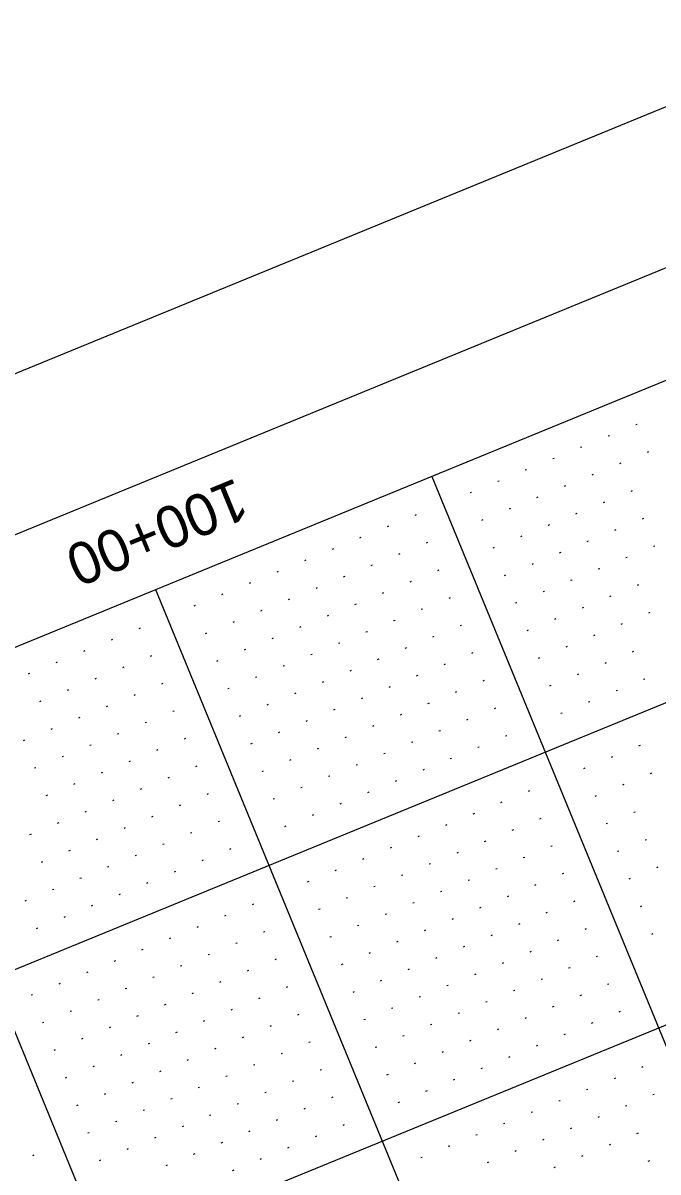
# Model space of a CAD drawing. Extents: x 2148770 to 2150891, y 142633 to 144465.
# Drawn here: x 2149510.3 to 2149616.7, y 143849.5 to 144042.2 of the extents above; entities that cross this region are included whole.
import ezdxf

# ---------------------------------------------------------------- set-up
doc = ezdxf.new("R2010")
doc.units = 0
for name, color, linetype in [('SHT_Plan_Profile_Sheet_Sta_Txt', 7, 'Continuous'), ('SHT_Plot_Shape_Half', 7, 'Continuous'), ('SHT_Profile_Grid_Major', 7, 'Continuous'), ('SHT_Profile_Grid_Minor', 7, 'Continuous'), ('SHT_Sheet_Border', 7, 'Continuous')]:
    doc.layers.add(name, color=color, linetype=linetype)

msp = doc.modelspace()

# ---------------------------------------------------------------- linework, layer by layer
at = {"layer": 'SHT_Plot_Shape_Half'}
msp.add_lwpolyline([(2150799.14, 143324.02), (2149226.52, 142678.36), (2148808.74, 143695.93), (2150381.36, 144341.59)], close=True, dxfattribs=at)
at = {"layer": 'SHT_Profile_Grid_Major'}
for p, q in [((2150326.3, 144218.99), (2148869.31, 143620.81)), ((2150345.29, 144172.74), (2148888.3, 143574.55)), ((2149578.81, 143966.15), (2149751.62, 143545.25)), ((2149532.56, 143947.16), (2149722.46, 143484.63)), ((2149532.56, 143947.16), (2149722.46, 143484.63)), ((2149486.31, 143928.17), (2149676.21, 143465.64))]:
    msp.add_line(p, q, dxfattribs=at)
at = {"layer": 'SHT_Profile_Grid_Minor'}
for p, q in [((2149613.21, 143974.87), (2149612.97, 143974.77)), ((2149608.58, 143972.97), (2149608.35, 143972.87)), ((2149603.96, 143971.07), (2149603.72, 143970.97)), ((2149599.33, 143969.17), (2149599.1, 143969.08)), ((2149615.1, 143970.24), (2149614.87, 143970.15)), ((2149594.7, 143967.27), (2149594.47, 143967.18)), ((2149610.48, 143968.34), (2149610.25, 143968.25)), ((2149590.08, 143965.37), (2149589.85, 143965.28)), ((2149605.85, 143966.44), (2149605.62, 143966.35)), ((2149585.45, 143963.47), (2149585.22, 143963.38)), ((2149601.23, 143964.55), (2149601, 143964.45)), ((2149612.38, 143963.72), (2149612.15, 143963.62)), ((2149596.6, 143962.65), (2149596.37, 143962.55)), ((2149607.75, 143961.82), (2149607.52, 143961.72)), ((2149576.2, 143959.68), (2149575.97, 143959.58)), ((2149591.98, 143960.75), (2149591.75, 143960.65)), ((2149603.13, 143959.92), (2149602.9, 143959.82)), ((2149571.58, 143957.78), (2149571.35, 143957.68)), ((2149587.35, 143958.85), (2149587.12, 143958.75)), ((2149598.5, 143958.02), (2149598.27, 143957.93)), ((2149614.28, 143959.09), (2149614.05, 143959)), ((2149566.95, 143955.88), (2149566.72, 143955.78)), ((2149593.88, 143956.12), (2149593.65, 143956.03)), ((2149605.03, 143955.29), (2149604.8, 143955.2)), ((2149609.65, 143957.19), (2149609.42, 143957.1)), ((2149562.33, 143953.98), (2149562.1, 143953.88)), ((2149578.1, 143955.05), (2149577.87, 143954.96)), ((2149589.25, 143954.22), (2149589.02, 143954.13)), ((2149600.4, 143953.4), (2149600.17, 143953.3)), ((2149616.18, 143954.47), (2149615.95, 143954.37)), ((2149557.7, 143952.08), (2149557.47, 143951.98)), ((2149573.48, 143953.15), (2149573.25, 143953.06)), ((2149595.78, 143951.5), (2149595.54, 143951.4)), ((2149611.55, 143952.57), (2149611.32, 143952.47)), ((2149553.08, 143950.18), (2149552.85, 143950.09)), ((2149568.85, 143951.25), (2149568.62, 143951.16)), ((2149580, 143950.42), (2149579.77, 143950.33)), ((2149591.15, 143949.6), (2149590.92, 143949.5)), ((2149606.93, 143950.67), (2149606.69, 143950.57)), ((2149548.45, 143948.28), (2149548.22, 143948.19)), ((2149564.23, 143949.35), (2149563.99, 143949.26)), ((2149575.38, 143948.53), (2149575.14, 143948.43)), ((2149602.3, 143948.77), (2149602.07, 143948.68)), ((2149613.45, 143947.94), (2149613.22, 143947.85)), ((2149543.83, 143946.38), (2149543.59, 143946.29)), ((2149559.6, 143947.45), (2149559.37, 143947.36)), ((2149570.75, 143946.63), (2149570.52, 143946.53)), ((2149581.9, 143945.8), (2149581.67, 143945.7)), ((2149597.68, 143946.87), (2149597.44, 143946.78)), ((2149608.82, 143946.04), (2149608.59, 143945.95)), ((2149539.2, 143944.48), (2149538.97, 143944.39)), ((2149554.98, 143945.56), (2149554.74, 143945.46)), ((2149566.13, 143944.73), (2149565.89, 143944.63)), ((2149577.27, 143943.9), (2149577.04, 143943.81)), ((2149593.05, 143944.97), (2149592.82, 143944.88)), ((2149604.2, 143944.14), (2149603.97, 143944.05)), ((2149550.35, 143943.66), (2149550.12, 143943.56)), ((2149561.5, 143942.83), (2149561.27, 143942.73)), ((2149572.65, 143942), (2149572.42, 143941.91)), ((2149599.57, 143942.25), (2149599.34, 143942.15)), ((2149615.35, 143943.32), (2149615.12, 143943.22)), ((2149529.95, 143940.69), (2149529.72, 143940.59)), ((2149545.72, 143941.76), (2149545.49, 143941.66)), ((2149556.87, 143940.93), (2149556.64, 143940.83)), ((2149568.02, 143940.1), (2149567.79, 143940.01)), ((2149583.8, 143941.17), (2149583.57, 143941.08)), ((2149594.95, 143940.35), (2149594.72, 143940.25)), ((2149610.72, 143941.42), (2149610.49, 143941.32)), ((2149525.32, 143938.79), (2149525.09, 143938.69)), ((2149541.1, 143939.86), (2149540.87, 143939.76)), ((2149552.25, 143939.03), (2149552.02, 143938.94)), ((2149563.4, 143938.2), (2149563.17, 143938.11)), ((2149579.17, 143939.28), (2149578.94, 143939.18)), ((2149606.1, 143939.52), (2149605.87, 143939.42)), ((2149520.7, 143936.89), (2149520.47, 143936.79)), ((2149531.85, 143936.06), (2149531.62, 143935.97)), ((2149547.62, 143937.13), (2149547.39, 143937.04)), ((2149558.77, 143936.3), (2149558.54, 143936.21)), ((2149574.55, 143937.38), (2149574.32, 143937.28)), ((2149585.7, 143936.55), (2149585.47, 143936.45)), ((2149601.47, 143937.62), (2149601.24, 143937.53)), ((2149612.62, 143936.79), (2149612.39, 143936.7)), ((2149516.07, 143934.99), (2149515.84, 143934.89)), ((2149527.22, 143934.16), (2149526.99, 143934.07)), ((2149543, 143935.23), (2149542.77, 143935.14)), ((2149554.15, 143934.41), (2149553.92, 143934.31)), ((2149569.92, 143935.48), (2149569.69, 143935.38)), ((2149581.07, 143934.65), (2149580.84, 143934.55)), ((2149596.85, 143935.72), (2149596.62, 143935.63)), ((2149608, 143934.89), (2149607.77, 143934.8)), ((2149511.45, 143933.09), (2149511.22, 143932.99)), ((2149522.6, 143932.26), (2149522.37, 143932.17)), ((2149549.52, 143932.51), (2149549.29, 143932.41)), ((2149565.3, 143933.58), (2149565.07, 143933.48)), ((2149576.45, 143932.75), (2149576.22, 143932.66)), ((2149603.37, 143933), (2149603.14, 143932.9)), ((2149517.97, 143930.36), (2149517.74, 143930.27)), ((2149533.75, 143931.43), (2149533.52, 143931.34)), ((2149544.9, 143930.61), (2149544.67, 143930.51)), ((2149560.67, 143931.68), (2149560.44, 143931.58)), ((2149571.82, 143930.85), (2149571.59, 143930.76)), ((2149587.6, 143931.92), (2149587.37, 143931.83)), ((2149598.75, 143931.1), (2149598.52, 143931)), ((2149609.9, 143930.27), (2149609.67, 143930.17)), ((2149614.52, 143932.17), (2149614.29, 143932.07)), ((2149513.35, 143928.46), (2149513.12, 143928.37)), ((2149529.12, 143929.54), (2149528.89, 143929.44)), ((2149556.05, 143929.78), (2149555.82, 143929.69)), ((2149567.2, 143928.95), (2149566.97, 143928.86)), ((2149582.97, 143930.02), (2149582.74, 143929.93)), ((2149605.27, 143928.37), (2149605.04, 143928.27)), ((2149524.5, 143927.64), (2149524.27, 143927.54)), ((2149535.65, 143926.81), (2149535.42, 143926.71)), ((2149551.42, 143927.88), (2149551.19, 143927.79)), ((2149562.57, 143927.05), (2149562.34, 143926.96)), ((2149578.35, 143928.13), (2149578.12, 143928.03)), ((2149589.5, 143927.3), (2149589.26, 143927.2)), ((2149600.65, 143926.47), (2149600.41, 143926.38)), ((2149519.87, 143925.74), (2149519.64, 143925.64)), ((2149531.02, 143924.91), (2149530.79, 143924.82)), ((2149546.8, 143925.98), (2149546.57, 143925.89)), ((2149557.95, 143925.15), (2149557.71, 143925.06)), ((2149573.72, 143926.23), (2149573.49, 143926.13)), ((2149584.87, 143925.4), (2149584.64, 143925.3)), ((2149515.25, 143923.84), (2149515.02, 143923.74)), ((2149526.4, 143923.01), (2149526.16, 143922.92)), ((2149553.32, 143923.26), (2149553.09, 143923.16)), ((2149569.1, 143924.33), (2149568.86, 143924.23)), ((2149580.25, 143923.5), (2149580.01, 143923.41)), ((2149591.4, 143922.67), (2149591.16, 143922.58)), ((2149510.62, 143921.94), (2149510.39, 143921.84)), ((2149521.77, 143921.11), (2149521.54, 143921.02)), ((2149537.55, 143922.18), (2149537.31, 143922.09)), ((2149548.7, 143921.36), (2149548.46, 143921.26)), ((2149564.47, 143922.43), (2149564.24, 143922.33)), ((2149575.62, 143921.6), (2149575.39, 143921.51)), ((2149586.77, 143920.77), (2149586.54, 143920.68)), ((2149613.69, 143921.02), (2149613.46, 143920.92)), ((2149517.15, 143919.21), (2149516.91, 143919.12)), ((2149532.92, 143920.29), (2149532.69, 143920.19)), ((2149559.85, 143920.53), (2149559.61, 143920.43)), ((2149570.99, 143919.7), (2149570.76, 143919.61)), ((2149582.14, 143918.87), (2149581.91, 143918.78)), ((2149609.07, 143919.12), (2149608.84, 143919.02)), ((2149512.52, 143917.31), (2149512.29, 143917.22)), ((2149528.29, 143918.39), (2149528.06, 143918.29)), ((2149539.44, 143917.56), (2149539.21, 143917.46)), ((2149555.22, 143918.63), (2149554.99, 143918.54)), ((2149566.37, 143917.8), (2149566.14, 143917.71)), ((2149577.52, 143916.98), (2149577.29, 143916.88)), ((2149604.44, 143917.22), (2149604.21, 143917.13)), ((2149523.67, 143916.49), (2149523.44, 143916.39)), ((2149534.82, 143915.66), (2149534.59, 143915.56)), ((2149550.59, 143916.73), (2149550.36, 143916.64)), ((2149561.74, 143915.9), (2149561.51, 143915.81)), ((2149572.89, 143915.08), (2149572.66, 143914.98)), ((2149615.59, 143916.39), (2149615.36, 143916.3)), ((2149519.04, 143914.59), (2149518.81, 143914.49)), ((2149530.19, 143913.76), (2149529.96, 143913.67)), ((2149541.34, 143912.93), (2149541.11, 143912.84)), ((2149557.12, 143914.01), (2149556.89, 143913.91)), ((2149568.27, 143913.18), (2149568.04, 143913.08)), ((2149595.19, 143913.42), (2149594.96, 143913.33)), ((2149610.97, 143914.49), (2149610.74, 143914.4)), ((2149514.42, 143912.69), (2149514.19, 143912.59)), ((2149525.57, 143911.86), (2149525.34, 143911.77)), ((2149536.72, 143911.03), (2149536.49, 143910.94)), ((2149552.49, 143912.11), (2149552.26, 143912.01)), ((2149563.64, 143911.28), (2149563.41, 143911.18)), ((2149590.57, 143911.52), (2149590.34, 143911.43)), ((2149606.34, 143912.59), (2149606.11, 143912.5)), ((2149520.94, 143909.96), (2149520.71, 143909.87)), ((2149532.09, 143909.14), (2149531.86, 143909.04)), ((2149559.02, 143909.38), (2149558.79, 143909.28)), ((2149585.94, 143909.62), (2149585.71, 143909.53)), ((2149612.87, 143909.87), (2149612.64, 143909.77)), ((2149516.32, 143908.06), (2149516.09, 143907.97)), ((2149527.47, 143907.24), (2149527.24, 143907.14)), ((2149543.24, 143908.31), (2149543.01, 143908.21)), ((2149554.39, 143907.48), (2149554.16, 143907.39)), ((2149581.32, 143907.73), (2149581.09, 143907.63)), ((2149597.09, 143908.8), (2149596.86, 143908.7)), ((2149608.24, 143907.97), (2149608.01, 143907.87)), ((2149511.69, 143906.16), (2149511.46, 143906.07)), ((2149522.84, 143905.34), (2149522.61, 143905.24)), ((2149538.62, 143906.41), (2149538.39, 143906.31)), ((2149576.69, 143905.83), (2149576.46, 143905.73)), ((2149592.47, 143906.9), (2149592.24, 143906.8)), ((2149614.77, 143905.24), (2149614.53, 143905.15)), ((2149518.22, 143903.44), (2149517.99, 143903.34)), ((2149533.99, 143904.51), (2149533.76, 143904.42)), ((2149545.14, 143903.68), (2149544.91, 143903.59)), ((2149572.07, 143903.93), (2149571.84, 143903.83)), ((2149587.84, 143905), (2149587.61, 143904.9)), ((2149598.99, 143904.17), (2149598.76, 143904.08)), ((2149610.14, 143903.34), (2149609.91, 143903.25)), ((2149513.59, 143901.54), (2149513.36, 143901.44)), ((2149529.37, 143902.61), (2149529.14, 143902.52)), ((2149540.52, 143901.78), (2149540.29, 143901.69)), ((2149567.44, 143902.03), (2149567.21, 143901.93)), ((2149583.22, 143903.1), (2149582.98, 143903)), ((2149594.37, 143902.27), (2149594.13, 143902.18)), ((2149524.74, 143900.71), (2149524.51, 143900.62)), ((2149535.89, 143899.88), (2149535.66, 143899.79)), ((2149562.82, 143900.13), (2149562.58, 143900.03)), ((2149578.59, 143901.2), (2149578.36, 143901.11)), ((2149589.74, 143900.37), (2149589.51, 143900.28)), ((2149600.89, 143899.55), (2149600.66, 143899.45)), ((2149616.67, 143900.62), (2149616.43, 143900.52)), ((2149520.12, 143898.81), (2149519.88, 143898.72)), ((2149531.27, 143897.99), (2149531.03, 143897.89)), ((2149558.19, 143898.23), (2149557.96, 143898.14)), ((2149573.97, 143899.3), (2149573.73, 143899.21)), ((2149585.12, 143898.47), (2149584.88, 143898.38)), ((2149596.26, 143897.65), (2149596.03, 143897.55)), ((2149612.04, 143898.72), (2149611.81, 143898.62)), ((2149515.49, 143896.91), (2149515.26, 143896.82)), ((2149526.64, 143896.09), (2149526.41, 143895.99)), ((2149569.34, 143897.4), (2149569.11, 143897.31)), ((2149580.49, 143896.58), (2149580.26, 143896.48)), ((2149591.64, 143895.75), (2149591.41, 143895.65)), ((2149510.87, 143895.02), (2149510.63, 143894.92)), ((2149522.01, 143894.19), (2149521.78, 143894.09)), ((2149548.94, 143894.43), (2149548.71, 143894.34)), ((2149564.71, 143895.5), (2149564.48, 143895.41)), ((2149575.86, 143894.68), (2149575.63, 143894.58)), ((2149587.01, 143893.85), (2149586.78, 143893.75)), ((2149602.79, 143894.92), (2149602.56, 143894.83)), ((2149613.94, 143894.09), (2149613.71, 143894)), ((2149517.39, 143892.29), (2149517.16, 143892.19)), ((2149544.31, 143892.53), (2149544.08, 143892.44)), ((2149560.09, 143893.6), (2149559.86, 143893.51)), ((2149571.24, 143892.78), (2149571.01, 143892.68)), ((2149582.39, 143891.95), (2149582.16, 143891.86)), ((2149598.16, 143893.02), (2149597.93, 143892.93)), ((2149512.76, 143890.39), (2149512.53, 143890.29)), ((2149539.69, 143890.63), (2149539.46, 143890.54)), ((2149550.84, 143889.81), (2149550.61, 143889.71)), ((2149566.61, 143890.88), (2149566.38, 143890.78)), ((2149577.76, 143890.05), (2149577.53, 143889.96)), ((2149593.54, 143891.12), (2149593.31, 143891.03)), ((2149604.69, 143890.3), (2149604.46, 143890.2)), ((2149535.06, 143888.74), (2149534.83, 143888.64)), ((2149546.21, 143887.91), (2149545.98, 143887.81)), ((2149561.99, 143888.98), (2149561.76, 143888.88)), ((2149573.14, 143888.15), (2149572.91, 143888.06)), ((2149588.91, 143889.22), (2149588.68, 143889.13)), ((2149600.06, 143888.4), (2149599.83, 143888.3)), ((2149615.84, 143889.47), (2149615.61, 143889.37)), ((2149530.44, 143886.84), (2149530.21, 143886.74)), ((2149541.59, 143886.01), (2149541.36, 143885.91)), ((2149568.51, 143886.25), (2149568.28, 143886.16)), ((2149584.29, 143887.32), (2149584.06, 143887.23)), ((2149595.44, 143886.5), (2149595.21, 143886.4)), ((2149525.81, 143884.94), (2149525.58, 143884.84)), ((2149536.96, 143884.11), (2149536.73, 143884.01)), ((2149552.74, 143885.18), (2149552.51, 143885.09)), ((2149563.89, 143884.35), (2149563.66, 143884.26)), ((2149579.66, 143885.43), (2149579.43, 143885.33)), ((2149590.81, 143884.6), (2149590.58, 143884.5)), ((2149606.59, 143885.67), (2149606.36, 143885.58)), ((2149521.19, 143883.04), (2149520.96, 143882.94)), ((2149532.34, 143882.21), (2149532.11, 143882.12)), ((2149548.11, 143883.28), (2149547.88, 143883.19)), ((2149575.04, 143883.53), (2149574.81, 143883.43)), ((2149586.19, 143882.7), (2149585.96, 143882.6)), ((2149601.96, 143883.77), (2149601.73, 143883.68)), ((2149516.56, 143881.14), (2149516.33, 143881.04)), ((2149527.71, 143880.31), (2149527.48, 143880.22)), ((2149543.49, 143881.38), (2149543.26, 143881.29)), ((2149554.64, 143880.56), (2149554.41, 143880.46)), ((2149570.41, 143881.63), (2149570.18, 143881.53)), ((2149581.56, 143880.8), (2149581.33, 143880.71)), ((2149597.34, 143881.87), (2149597.11, 143881.78)), ((2149608.49, 143881.04), (2149608.25, 143880.95)), ((2149511.94, 143879.24), (2149511.71, 143879.15)), ((2149523.09, 143878.41), (2149522.86, 143878.32)), ((2149538.86, 143879.48), (2149538.63, 143879.39)), ((2149550.01, 143878.66), (2149549.78, 143878.56)), ((2149565.79, 143879.73), (2149565.56, 143879.63)), ((2149576.94, 143878.9), (2149576.7, 143878.81)), ((2149592.71, 143879.97), (2149592.48, 143879.88)), ((2149603.86, 143879.15), (2149603.63, 143879.05)), ((2149518.46, 143876.51), (2149518.23, 143876.42)), ((2149534.24, 143877.59), (2149534.01, 143877.49)), ((2149545.39, 143876.76), (2149545.15, 143876.66)), ((2149572.31, 143877), (2149572.08, 143876.91)), ((2149588.09, 143878.07), (2149587.85, 143877.98)), ((2149599.24, 143877.25), (2149599, 143877.15)), ((2149610.39, 143876.42), (2149610.15, 143876.32)), ((2149513.84, 143874.61), (2149513.6, 143874.52)), ((2149529.61, 143875.69), (2149529.38, 143875.59)), ((2149540.76, 143874.86), (2149540.53, 143874.76)), ((2149556.54, 143875.93), (2149556.3, 143875.84)), ((2149567.69, 143875.1), (2149567.45, 143875.01)), ((2149583.46, 143876.18), (2149583.23, 143876.08)), ((2149594.61, 143875.35), (2149594.38, 143875.25)), ((2149605.76, 143874.52), (2149605.53, 143874.43)), ((2149524.99, 143873.79), (2149524.75, 143873.69)), ((2149536.14, 143872.96), (2149535.9, 143872.87)), ((2149551.91, 143874.03), (2149551.68, 143873.94)), ((2149578.84, 143874.28), (2149578.6, 143874.18)), ((2149589.98, 143873.45), (2149589.75, 143873.35)), ((2149601.13, 143872.62), (2149600.9, 143872.53)), ((2149520.36, 143871.89), (2149520.13, 143871.79)), ((2149531.51, 143871.06), (2149531.28, 143870.97)), ((2149547.29, 143872.13), (2149547.05, 143872.04)), ((2149558.43, 143871.31), (2149558.2, 143871.21)), ((2149574.21, 143872.38), (2149573.98, 143872.28)), ((2149585.36, 143871.55), (2149585.13, 143871.45)), ((2149596.51, 143870.72), (2149596.28, 143870.63)), ((2149515.74, 143869.99), (2149515.5, 143869.89)), ((2149526.88, 143869.16), (2149526.65, 143869.07)), ((2149542.66, 143870.23), (2149542.43, 143870.14)), ((2149553.81, 143869.41), (2149553.58, 143869.31)), ((2149569.58, 143870.48), (2149569.35, 143870.38)), ((2149580.73, 143869.65), (2149580.5, 143869.56)), ((2149591.88, 143868.82), (2149591.65, 143868.73)), ((2149522.26, 143867.26), (2149522.03, 143867.17)), ((2149538.03, 143868.33), (2149537.8, 143868.24)), ((2149549.18, 143867.51), (2149548.95, 143867.41)), ((2149560.33, 143866.68), (2149560.1, 143866.59)), ((2149576.11, 143867.75), (2149575.88, 143867.66)), ((2149587.26, 143866.92), (2149587.03, 143866.83)), ((2149614.18, 143867.17), (2149613.95, 143867.07)), ((2149517.63, 143865.36), (2149517.4, 143865.27)), ((2149533.41, 143866.44), (2149533.18, 143866.34)), ((2149544.56, 143865.61), (2149544.33, 143865.51)), ((2149555.71, 143864.78), (2149555.48, 143864.69)), ((2149571.48, 143865.85), (2149571.25, 143865.76)), ((2149582.63, 143865.03), (2149582.4, 143864.93)), ((2149609.56, 143865.27), (2149609.33, 143865.17)), ((2149528.78, 143864.54), (2149528.55, 143864.44)), ((2149539.93, 143863.71), (2149539.7, 143863.61)), ((2149551.08, 143862.88), (2149550.85, 143862.79)), ((2149578.01, 143863.13), (2149577.78, 143863.03)), ((2149604.93, 143863.37), (2149604.7, 143863.28)), ((2149524.16, 143862.64), (2149523.93, 143862.54)), ((2149535.31, 143861.81), (2149535.08, 143861.72)), ((2149546.46, 143860.98), (2149546.23, 143860.89)), ((2149562.23, 143862.05), (2149562, 143861.96)), ((2149573.38, 143861.23), (2149573.15, 143861.13)), ((2149600.31, 143861.47), (2149600.08, 143861.38)), ((2149616.08, 143862.54), (2149615.85, 143862.45)), ((2149519.53, 143860.74), (2149519.3, 143860.64)), ((2149530.68, 143859.91), (2149530.45, 143859.82)), ((2149541.83, 143859.08), (2149541.6, 143858.99)), ((2149557.61, 143860.16), (2149557.38, 143860.06)), ((2149595.68, 143859.57), (2149595.45, 143859.48)), ((2149611.46, 143860.64), (2149611.23, 143860.55)), ((2149526.06, 143858.01), (2149525.83, 143857.92)), ((2149537.21, 143857.19), (2149536.98, 143857.09)), ((2149552.98, 143858.26), (2149552.75, 143858.16)), ((2149564.13, 143857.43), (2149563.9, 143857.33)), ((2149591.06, 143857.67), (2149590.83, 143857.58)), ((2149606.83, 143858.75), (2149606.6, 143858.65)), ((2149521.43, 143856.11), (2149521.2, 143856.02)), ((2149532.58, 143855.29), (2149532.35, 143855.19)), ((2149548.36, 143856.36), (2149548.13, 143856.26)), ((2149559.51, 143855.53), (2149559.28, 143855.44)), ((2149586.43, 143855.77), (2149586.2, 143855.68)), ((2149602.21, 143856.85), (2149601.97, 143856.75)), ((2149613.36, 143856.02), (2149613.12, 143855.92)), ((2149527.96, 143853.39), (2149527.73, 143853.29)), ((2149543.73, 143854.46), (2149543.5, 143854.36)), ((2149554.88, 143853.63), (2149554.65, 143853.54)), ((2149581.81, 143853.88), (2149581.57, 143853.78)), ((2149597.58, 143854.95), (2149597.35, 143854.85)), ((2149608.73, 143854.12), (2149608.5, 143854.03)), ((2149512.18, 143852.32), (2149511.95, 143852.22)), ((2149523.33, 143851.49), (2149523.1, 143851.39)), ((2149539.11, 143852.56), (2149538.87, 143852.46)), ((2149550.26, 143851.73), (2149550.02, 143851.64)), ((2149577.18, 143851.98), (2149576.95, 143851.88)), ((2149592.96, 143853.05), (2149592.72, 143852.95)), ((2149604.11, 143852.22), (2149603.87, 143852.13)), ((2149615.25, 143851.39), (2149615.02, 143851.3)), ((2149534.48, 143850.66), (2149534.25, 143850.57)), ((2149545.63, 143849.83), (2149545.4, 143849.74)), ((2149588.33, 143851.15), (2149588.1, 143851.05)), ((2149599.48, 143850.32), (2149599.25, 143850.23))]:
    msp.add_line(p, q, dxfattribs=at)
at = {"layer": 'SHT_Sheet_Border'}
msp.add_line((2150307.31, 144265.25), (2149093.15, 143766.76), dxfattribs=at)
msp.add_lwpolyline([(2150699.45, 143310.11), (2149242.47, 142711.93), (2148843.68, 143683.25), (2150300.66, 144281.43)], close=True, dxfattribs=at)

# ---------------------------------------------------------------- texts
at = {"layer": 'SHT_Plan_Profile_Sheet_Sta_Txt'}
msp.add_text('100+00', height=7, rotation=202.3213, dxfattribs=at).set_placement((2149546.07, 143965.95))

doc.saveas('drawing.dxf')
